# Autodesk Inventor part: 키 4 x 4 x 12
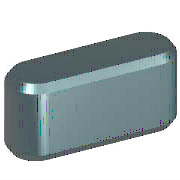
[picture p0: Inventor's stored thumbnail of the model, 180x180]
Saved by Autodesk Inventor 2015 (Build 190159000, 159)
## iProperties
IsCustomPart: 1
Created: 2012-02
Part Number: 키 4 x 4 x 12
Material: 강철, 연강
Description: 키 및 해당 키홈
Document SubType Name: Modeling
Standard: KS B 1311
Designer: mduedu
Standards Organization: KS
Language: ko-KR
Size Designation: 4 x 4 x 12
Categories: <MemberInstance><Categories><Category DisplayName="샤프트 부품" InternalName="7f7aeb1f-a693-4053-b835-cee3144e0d98" Mnemonic="SHFT"><Category DisplayName="키" Interna
Density: 7.85 g/cm^3
Appearance: 노란색
Mass: 1.38563 g
Surface Area: 1.94869 cm^2
Volume: 0.176513 cm^3
Author: mduedu
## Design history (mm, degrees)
workplane "Work Plane1"
workplane "Work Plane2"
sketch "스케치1"
  geometry: L1 (2, 2)-(10, 2); L2 (10, -2)-(2, -2); L3 (0, 9.4)-(0, -7.4) reference; L4 (-5, 0)-(30, 0) reference; L5 (12, 0)-(12, 7); A1 r 2 centre (2, 0) between (2, 2) and (2, -2); A2 r 2 centre (10, 0) between (10, -2) and (10, 2)
  constraints: 6 end point, 5 point on circle, 4 tangent, 3 point on line, 2 centre point, 1 horizontal, 1 parallel, 1 perpendicular
  dimensions: "d0" = 2 radius of A1 (= 0.5 x PB); "d13" = 2 radius of A2 (= 0.5 x PB); "d14" = 12 distance between parallel lines of L5 L3 (= NLG)
extrude "본체1" new body sketch "스케치1" taper "d3" = 0 deg; stored distance "d4" = 10
workplane "Work Plane3"
body "Solid1"
chamfer "모따기1" distance "d8" = 0.25 (= PHH); stored, may be unused: second distance "d9" = 0.25 (= PHH), angle "d15" = 45 deg
other parameters: "d1" = -2.5 (= -PNT), "d2" = 1.5 (= PH - PNT), "NLG" = 12 [user parameter; used in 3 equation terms], "PB" = 4 [user parameter; used in 2 equation terms], "PNT" = 2.5 [user parameter; used in 2 equation terms], "PH" = 4 [user parameter; used in 1 equation term], "PHH" = 0.25 [user parameter; used in 2 equation terms], "d10" = 0, "d16" = 0, "d17" = 0, "d18" = 0, "PLB2" = 12 (= NLG) [user parameter], "WDMAX" = 12 [user parameter], "PLB1" = 12 (= NLG) [user parameter], "RR" = 0.08 [user parameter], "PUEB" = 1.8 [user parameter]
